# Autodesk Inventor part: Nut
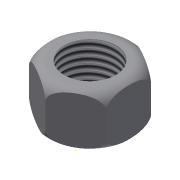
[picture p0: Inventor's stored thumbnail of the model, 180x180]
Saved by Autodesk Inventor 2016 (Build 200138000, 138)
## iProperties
Created: 2010-03
Part Number: Nut
Document SubType Name: Modeling
Designer: bhakira
Density: 1 g/cm^3
Material: Generic
Appearance: Default
Author: bhakira
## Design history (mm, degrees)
sketch "Sketch1"
  geometry: L1 (0, 17.321)-(15, 8.66); L2 (15, 8.66)-(15, -8.66); L3 (15, -8.66)-(0, -17.321); L4 (0, -17.321)-(-15, -8.66); L5 (-15, -8.66)-(-15, 8.66); L6 (-15, 8.66)-(0, 17.321); 2 further points
  constraints: 12 end point, 1 coincident, 13 other
  dimensions: "d0" = 30 distance between parallel lines of L2 L5
extrude "Extrusion1" new body sketch "Sketch1" distance "d1" = 20; taper "d2" = 0 deg
sketch "Sketch2"
  geometry: L1 (0, 17.321)-(-15, 8.66) reference; L2 (-15, 8.66)-(-15, -8.66) reference; L3 (-15, -8.66)-(0, -17.321) reference; L4 (0, -17.321)-(15, -8.66) reference; L5 (15, -8.66)-(15, 8.66) reference; L6 (15, 8.66)-(0, 17.321) reference
sketch "Sketch3"
  geometry: C1 r 10 at (0, 0); 1 further point
  constraints: 1 centre point, 1 coincident
  dimensions: "d4" = 20 diameter of C1
extrude "Extrusion2" cut sketch "Sketch3" stored distance "d5" = 15; taper "d6" = 0 deg
thread "Thread1" dims "d7" = 10, "d8" = 0
sketch "Sketch5"
  geometry: L1 (-17.321, 20)-(-8.66, 20) reference; L2 (-17.321, 20)-(-8.66, 20) reference; L3 (-8.66, 0)-(-8.66, 20) reference; L4 (-17.321, 0)-(-8.66, 0) reference; L5 (-17.321, 0)-(-17.321, 20) reference; L6 (0, -8)-(0, 24); L7 (-12.035, 20)-(-17.321, 20); A1 r 5.286 centre (-12.035, 14.714) between (-12.035, 20) and (-17.321, 14.714); 1 further point
  constraints: 4 end point, 3 tangent, 2 point on circle, 2 point on line, 1 centre point, 1 collinear, 1 parallel
revolve "Revolution1" sketch "Sketch5" stored, may be unused: angle "d16" = 90 deg
sketch "Sketch6"
  geometry: 1 further point
workplane "Work Plane1"
mirror "Mirror1"
body "Solid1"
node "Projected Loop1"
